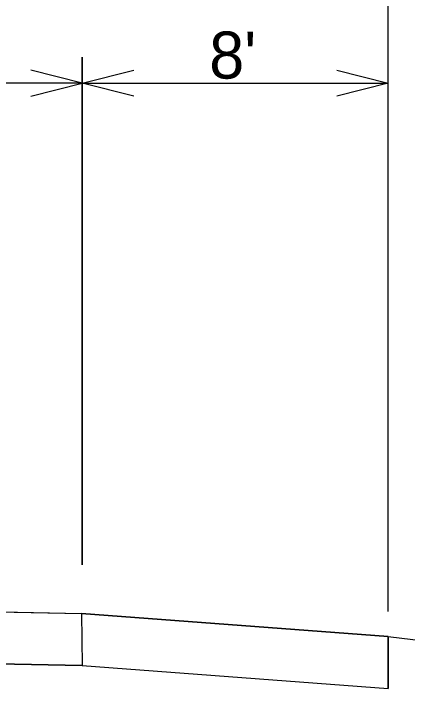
# Model space of a CAD drawing. Extents: x 10133 to 81668, y 4856 to 11018.
# Drawn here: x 15476.8 to 15602.2, y 9465.2 to 9680.3 of the extents above; entities that cross this region are included whole.
import ezdxf

# ---------------------------------------------------------------- set-up
doc = ezdxf.new("R2010")
doc.units = 0
for name, color, linetype in [('dsnXsPCCPavementBottom', 7, 'Continuous'), ('dsnXsShldrEarthFill', 7, 'Continuous'), ('dsnXsShldrGranular', 7, 'Continuous'), ('dsnXsShldrGranularBottom', 7, 'Continuous'), ('dsnXsShldrSpecialBackBottom', 7, 'Continuous')]:
    doc.layers.add(name, color=color, linetype=linetype)

msp = doc.modelspace()

# ---------------------------------------------------------------- linework, layer by layer
at = {"layer": 'dsnXsPCCPavementBottom'}
for p, q in [((15596.08, 9489.65), (15596.08, 9754.76)), ((15498.67, 9504.52), (15498.67, 9666.39)), ((15498.67, 9666.39), (15498.67, 9504.52)), ((15498.67, 9666.39), (15498.67, 9504.52)), ((15498.67, 9658.07), (15299.76, 9658.07)), ((15498.67, 9658.07), (15596.08, 9658.07))]:
    msp.add_line(p, q, dxfattribs=at)
for points in [[(15482.28, 9653.97), (15498.67, 9658.07), (15482.28, 9662.17)], [(15515.06, 9653.97), (15498.67, 9658.07), (15515.06, 9662.17)], [(15579.69, 9662.17), (15596.08, 9658.07), (15579.69, 9653.97)]]:
    msp.add_lwpolyline(points, dxfattribs=at)
at = {"layer": 'dsnXsShldrGranular'}
msp.add_line((15498.67, 9472.47), (15299.65, 9476.7), dxfattribs=at)
msp.add_lwpolyline([(15300, 9493.25), (15498.43, 9489.03), (15498.67, 9472.47)], dxfattribs=at)
msp.add_lwpolyline([(15596.08, 9481.76), (15498.43, 9489.03), (15498.67, 9472.47), (15596.08, 9465.16)], close=True, dxfattribs=at)
at = {"layer": 'dsnXsShldrGranularBottom'}
for p, q in [((15300, 9493.25), (15498.43, 9489.03)), ((15498.43, 9489.03), (15498.67, 9472.47)), ((15498.43, 9489.03), (15498.67, 9472.47)), ((15498.43, 9489.03), (15498.67, 9472.47)), ((15498.43, 9489.03), (15498.67, 9472.47)), ((15596.08, 9481.76), (15719.19, 9466.29)), ((15299.65, 9476.7), (15498.67, 9472.47))]:
    msp.add_line(p, q, dxfattribs=at)
at = {"layer": 'dsnXsShldrSpecialBackBottom'}
for p, q in [((15498.43, 9489.03), (15596.08, 9481.76)), ((15596.08, 9481.76), (15596.08, 9465.16)), ((15498.67, 9472.47), (15596.08, 9465.16))]:
    msp.add_line(p, q, dxfattribs=at)

# ---------------------------------------------------------------- texts
at = {"layer": 'dsnXsShldrEarthFill'}
msp.add_text("8'", height=15, rotation=0, dxfattribs=at).set_placement((15539.1, 9659.53))

doc.saveas('drawing.dxf')
